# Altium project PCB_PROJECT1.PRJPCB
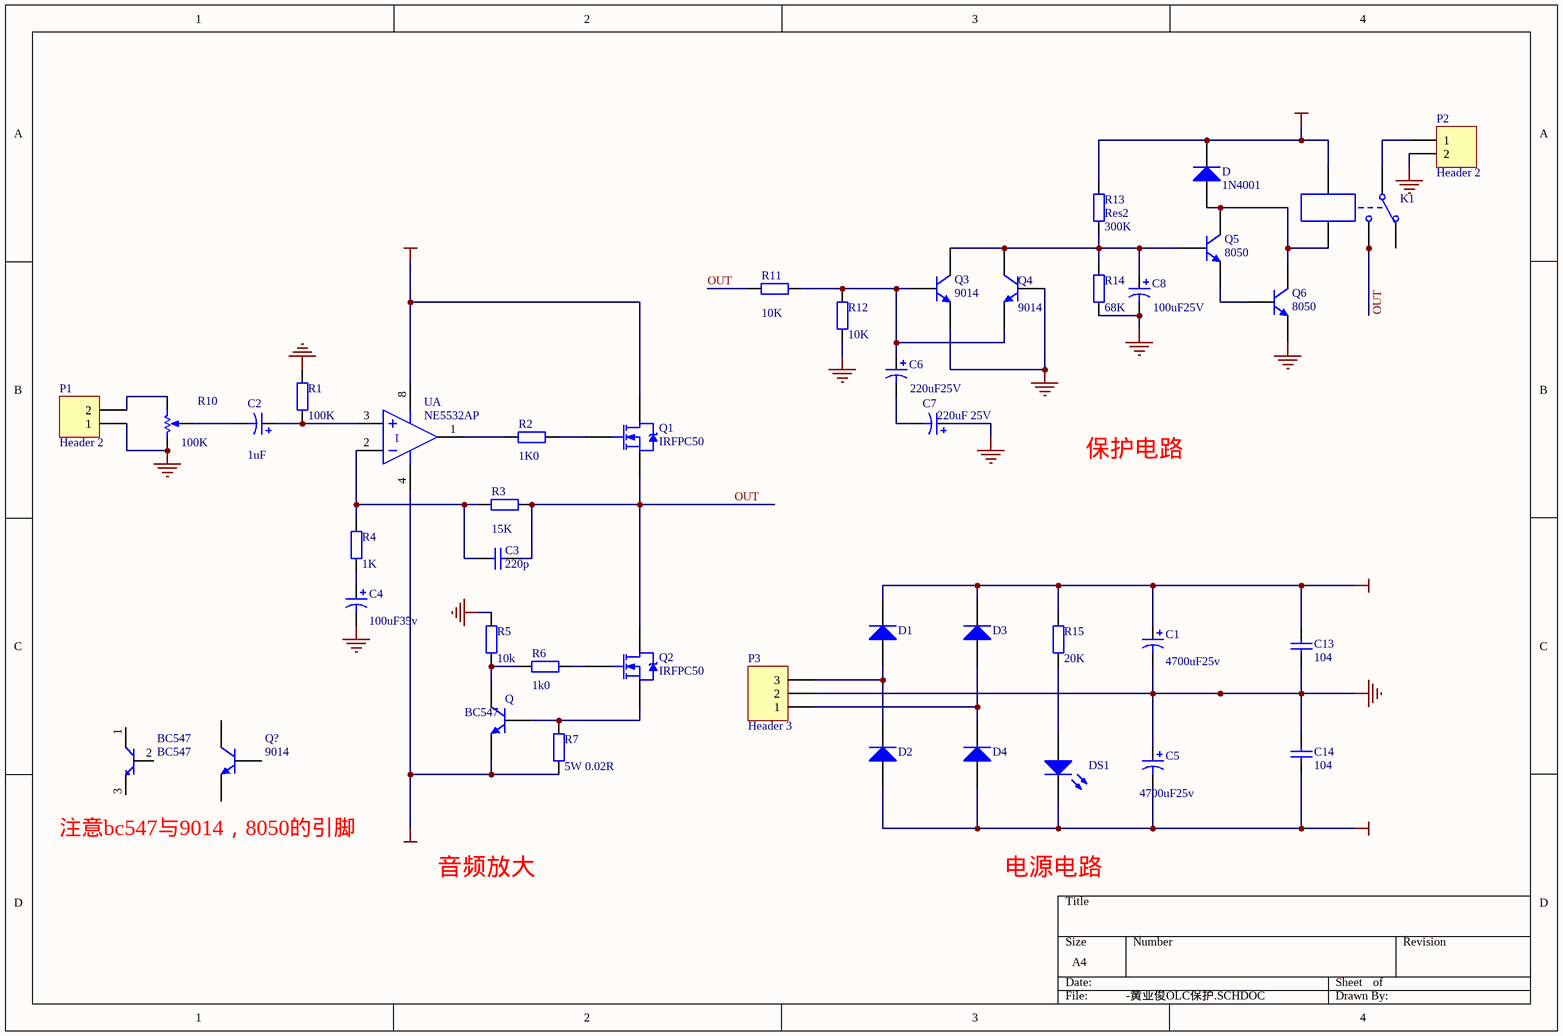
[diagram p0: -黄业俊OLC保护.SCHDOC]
1 sheet, 43 parts. Net scope: global (net labels, ports and power ports of the same name join across sheets).
Board files: -黄业俊PCB.PcbDoc, PCB1.PCBDOC

## Sheet -黄业俊OLC保护.SCHDOC
size A4

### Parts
BC547  BC547
C1  value 4700uF25v  [RB7.6-15]  (hidden comment: Cap Pol1)
C2  value 1uF  [CAPPR2-5x6.8]  (hidden comment: Cap Pol1)
C3  value 220p  [AXIAL-0.4]  (hidden comment: Cap)
C4  value 100uF35v  [CAPPR2-5x6.8]  (hidden comment: Cap Pol1)
C5  value 4700uF25v  [RB7.6-15]  (hidden comment: Cap Pol1)
C6  value 220uF25V  [CAPPR2-5x6.8]  (hidden comment: Cap Pol1)
C7  value 220uF 25V  [CAPPR2-5x6.8]  (hidden comment: Cap Pol1)
C8  value 100uF25V  [CAPPR2-5x6.8]  (hidden comment: Cap Pol1)
C13  value 104  [CAPR5-4X5]  (hidden comment: Cap)
C14  value 104  [CAPR5-4X5]  (hidden comment: Cap)
D  1N4001  [DIO10.46-5.3x2.8]
D1  Diode 1N914  [DIO7.1-3.9x1.9]  (value not drawn)
D2  Diode 1N914  [DIO7.1-3.9x1.9]  (value not drawn)
D3  Diode 1N914  [DIO7.1-3.9x1.9]  (value not drawn)
D4  Diode 1N914  [DIO7.1-3.9x1.9]  (value not drawn)
DS1  LED0  [CAPPR1.5-4x5]  (value not drawn)
K1  Relay-SPDT  [jidianqi]  (value not drawn)
P1  Header 2  [音频线]
P2  Header 2  [pcZOU]
P3  Header 3  [duanzi]
Q  BC547  [BCY-W3/E4]
Q1  IRFPC50  [TO-247AC]
Q2  IRFPC50  [TO-247AC]
Q3  9014  [BCY-W3/E4]
Q4  9014  [BCY-W3/E4]
Q5  8050  [BCY-W3/E4]
Q6  8050  [BCY-W3/E4]
Q?  9014  [BCY-W3/E4]
R1  value 100K  [AXIAL-0.4]  (hidden comment: Res2)
R2  value 1K0  [AXIAL-0.4]  (hidden comment: Res2)
R3  value 15K  [AXIAL-0.4]  (hidden comment: Res2)
R4  value 1K  [AXIAL-0.4]  (hidden comment: Res2)
R5  value 10k  [AXIAL-0.4]  (hidden comment: Res2)
R6  value 1k0  [AXIAL-0.4]  (hidden comment: Res2)
R7  value 5W 0.02R  [0.02r   5W]  (hidden comment: Res2)
R10  value 100K  [电位器]
R11  value 10K  [AXIAL-0.4]  (hidden comment: Res2)
R12  value 10K  [AXIAL-0.4]  (hidden comment: Res2)
R13  Res2  value 300K  [AXIAL-0.4]
R14  value 68K  [AXIAL-0.4]  (hidden comment: Res2)
R15  value 20K  [AXIAL-0.4]  (hidden comment: Res2)
U  NE5532AP  [P008]  (part A of 2)

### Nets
+12V: C1.1 C13.1 D.2(K) D1.2(K) D3.2(K) K1.5 Q1.2(D) R13.1 R15.2 U.8(V+)
-12V: C5.2 C14.1 D2.1(A) D4.1(A) DS1.2(K) Q.3(E) R7.1 U.4(v-)
GND: C1.2 C4.2 C5.1 C7.1 C8.2 C13.2 C14.2 P1.1 P2.2 P3.2 Q3.1(E) Q4.2(B) Q6.1(E) R1.2 R5.1 R10.3(BOT) R12.2 R14.2
OUT: C3.2 K1.3 Q1.3(S) Q2.2(D) R3.2 R11.2
NetC2_1: C2.1 R1.1 U.3(IN+)
NetC2_2: C2.2 R10.2(TAP)
NetC3_1: C3.1 R3.1 R4.2 U.2(IN-)
NetC4_1: C4.1 R4.1
NetC6_1: C6.1 Q3.2(B) Q4.1(E) R11.1 R12.1
NetC6_2: C6.2 C7.2
NetC8_1: C8.1 Q3.3(C) Q4.3(C) Q5.2(B) R13.2 R14.1
NetD1_1: D1.1(A) D2.2(K) P3.3
NetD3_1: D3.1(A) D4.2(K) P3.1
NetD_1: D.1(A) K1.4 Q5.3(C) Q6.3(C)
NetDS1_1: DS1.1(A) R15.1
NetK1_1: K1.1 P2.1
NetP1_2: P1.2 R10.1(TOP)
NetQ1_1: Q1.1(G) R2.2
NetQ2_1: Q2.1(G) R6.2
NetQ5_1: Q5.1(E) Q6.2(B)
NetQ_1: Q.1(C) R5.2 R6.1
NetQ_2: Q.2(B) Q2.3(S) R7.2
NetR2_1: R2.1 U.1(OUT)

Not connected (* = marked no-connect by the designer): BC547 1 2 3; K1 2; Q? 1(E) 2(B) 3(C)

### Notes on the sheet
- 保护电路
- 注意bc547与9014，8050的引脚
- 音频放大
- 电源电路

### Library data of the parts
C1 C2 C4-C8 = Cap Pol1: Polarized Capacitor (Radial)
C3 C13 C14 = Cap: Capacitor
D = Diode 1N4001: 1 Amp General Purpose Rectifier
D1-D4 = Diode 1N914: High Conductance Fast Diode
DS1 = LED0: Typical INFRARED GaAs LED
K1 = Relay-SPDT: Single-Pole Dual-Throw Relay
P1 P2 = Header 2: Header, 2-Pin
P3 = Header 3: Header, 3-Pin
Q Q3-Q6 Q? = 2N3904: NPN General Purpose Amplifier
Q1 Q2 = IRFPC50: HEXFET Power MOSFET; Note: Pin 2 is electrically connected to the Heatsink (4).
R1-R7 R11-R15 = Res2: Resistor
R10 = RPot: Potentiometer; Sim Note: Enter the Resistance value and the set point into parameter fields.; Set Position: 0.5
U = NE5532AP: Dual Low-Noise Operational Amplifier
